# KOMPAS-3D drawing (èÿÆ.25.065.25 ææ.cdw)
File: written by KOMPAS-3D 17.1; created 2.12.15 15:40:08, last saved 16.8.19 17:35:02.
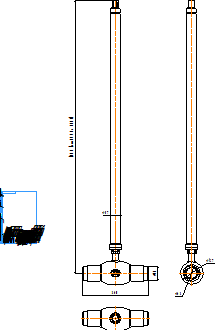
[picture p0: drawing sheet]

Sheet 1: A4, portrait

Title block, sheet 1: name: КШТ.25.065.25 С/С; sheets: 1; organisation: ООО "АДЛ Групп"; sheet format: A4; stored path: C:\Users\kka\KOMPAS_Work\Модели кранов для исследований\DN50\С удлинением\КШГ.32.050.40 СС ГЧ _ Шаровой кран БИВАЛ Ду50 Ру4 МПа редуцированный под приварку, с удлинением штока H=1100.cdw

Views: Вид 1, Проекционный вид 2, Проекционный вид 3
Referenced files in C:\Users\kka\KOMPAS_Work\Модели кранов для исследований\DN80\С удлинением\: КШТ.22.080.25 СС.a3d, КШГ.35.065.25 СС.a3d!КШГ.45.065.10 СС!Деталь (локальная).m3d
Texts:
  Klimkovich
  ADL
  (от 297 до 5000)
  Рама для чертежей
  Лит-Масса-Масштаб
  Материал-Предприятие
  Масштаб
  Изм.
  Лист
  № докум.
  Подп.
  Дата
  Лит.
  Разраб.
  Пров.
  Т.контр.
  Листов
  Внимание! Данный продукт является объектом авторского права ООО «Торговый Дом АДЛ».
  Запрещается изменение, копирование, распространение
  (в том числе путем копирования на другие сайты и ресурсы в Интернете)
  или любое иное использование информации и объектов без предварительного
  согласия правообладателя (ООО «Торговый Дом АДЛ»).
  Н.контр.
  Утв.
  ООО "Торговый дом АДЛ"
  Изменение
  Номер документа
  Подпись
  Обозначение документа
  Наименование изделия
  Масса изделия по ГОСТ 2.109-73
  Порядковый номер листа
  Общее количество листов в документе
  Характер работы, выполненной лицом, подписавшим документ
  Наименование или индекс предприятия, выпускающего документ
  Инв. № подл.
  Подп. и дата
  Взам. инв. №
  Инв. № дубл.
  Инвентарный номер подлинника по ГОСТ 2.501-68
  Подпись принявшего подлинник в отдел технической документации
  Инвентарный номер подлинника, взамен которого выпущен данный подлинник
  Инвентарный номер дубликата по ГОСТ 2.502-68
  Подпись принявшего дубликат в отдел технической документации
  Справ. №
  Перв. примен.
  Обозначение документа, взамен или на основании которого выпущен данный документ
  Обозначение документа, в котором впервые записан данный документ
  Подпись лица, копировавшего чертеж
  Обозначение формата листа
  !Рама для чертежа
Dimensions and other numbers on the sheet: 1500; 57; 76; 360; 63; 127; 1:1; 1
